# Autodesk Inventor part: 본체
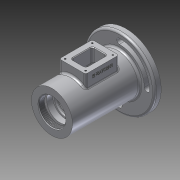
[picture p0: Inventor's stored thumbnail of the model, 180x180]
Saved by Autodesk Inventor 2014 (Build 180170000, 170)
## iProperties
Created: 2017-05
Part Number: 본체
Material: 알루미늄 6061
Document SubType Name: Modeling
Designer: oa51
Density: 2.71 g/cm^3
Appearance: 알루미늄 - 평지
Author: oa51
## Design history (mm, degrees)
sketch "스케치1"
  geometry: L1 (0, 57.5)-(0, -57.5); L2 (0, 57.5)-(31, 57.5); L3 (31, 57.5)-(31, -57.5); L4 (31, -57.5)-(22, -57.5); L5 (22, -57.5)-(16, -43.5); L6 (16, -43.5)-(12.904, -43.5); L7 (12.5, -36.2)-(10, -36.2); L8 (10, -36.2)-(10, -33.5); L9 (16.5, -33.5)-(16.5, -28.5); L10 (16.5, -28.5)-(17.5, -28.5); L11 (17.5, -28.5)-(17.5, -17.5); L12 (17.5, -17.5)-(26, -17.5); L13 (26, -17.5)-(26, 20.5); L14 (26, 20.5)-(17.5, 20.5); L15 (17.5, 20.5)-(17.5, 31.5); L16 (17.5, 31.5)-(18.5, 31.5); L17 (18.5, 31.5)-(18.5, 33.25); L18 (18.5, 33.25)-(17.5, 33.25); L19 (24, 48.5)-(0, 48.5); L20 (10, -33.5)-(16.5, -33.5); L21 (17.5, 33.25)-(17.5, 36.5); L22 (17.5, 36.5)-(20, 36.5); L23 (20, 36.5)-(20, 45.5); L24 (20, 45.5)-(24, 45.5); L25 (24, 45.5)-(24, 48.5); L26 (12.5, -36.2)-(12.5, -42.8); L27 (12.5, -42.8)-(12.904, -43.5); 2 further points
  constraints: 54 end point, 19 parallel, 5 perpendicular, 1 coincident, 1 horizontal alignment, 1 midpoint, 1 point on line, 1 vertical
  dimensions: "d0" = 115 distance of L1.start L1.end; "d1" = 62 diameter of L3 L1; "d2" = 32 diameter of L5.end L1; "d4" = 20 diameter of L8 L1; "d5" = 33 diameter of L9 L1; "d6" = 35 diameter of L11 L1; "d7" = 52 diameter of L13 L1; "d9" = 37 diameter of L17 L1; "d12" = 14 vertical distance of L1.end L5.end; "d14" = 7.3 vertical distance of L6.end L7.end; "d15" = 2.7 distance of L7.end L8.end; "d16" = 5 distance of L9.start L9.end; "d17" = 11 distance of L10.end L11.end; "d18" = 38 distance of L12.end L13.end; "d19" = 11 distance of L14.end L15.end; "d20" = 1.75 distance of L16.end L17.end; "d21" = 35 diameter of L15 L1; "d22" = 12 vertical distance of L23.end L1.start; "d23" = 3 distance of L24.end L19.start; "d24" = 48 diameter of L25 L1; "d25" = 40 diameter of L23 L1; "d26" = 35 diameter of L21 L1; "d27" = 21 vertical distance of L1.start L21.end; "d28" = 44 diameter of L4.end L1; "d62" = 30 deg angle of L26 L27; "d63" = 25 diameter of L26 L1; "d64" = 0.7 vertical distance of L6.end L26.end
revolve "회전1" sketch "스케치1" stored, may be unused: angle "d29" = 90 deg
hole "구멍1" diameter "d32" = 40.376; stored, may be unused: countersink angle "d36" = 90 deg, drill point angle "d38" = 0 deg; dims "d30" = 10, "d31" = 10, "d33" = 11, "d34" = 4, "d35" = 2, "d37" = 11
node "작업 평면1"
sketch "스케치2"
  geometry: L1 (20, 26.5)-(-20, 26.5); L2 (-20, 26.5)-(-20, -23.5); L3 (-20, -23.5)-(20, -23.5); L4 (20, -23.5)-(20, 26.5); L5 (-31, 57.5)-(31, 57.5) reference; 2 further points
  constraints: 8 end point, 2 parallel, 1 horizontal, 1 midpoint, 1 perpendicular, 1 vertical alignment
  dimensions: "d40" = 40 distance of L3.end L2.end; "d41" = 50 distance of L2.end L1.end; "d42" = 31 distance between parallel lines of L5 L1
extrude "돌출1" join sketch "스케치2" stored distance "d43" = 10; taper "d44" = 0 deg
sketch "스케치3"
  geometry: L1 (-20, -26.5)-(20, -26.5) reference; L2 (-20, 23.5)-(-20, -26.5) reference; L3 (-11, -17.5)-(11, -17.5); L4 (11, -17.5)-(11, 14.5); L5 (11, 14.5)-(-11, 14.5); L6 (-11, 14.5)-(-11, -17.5); 5 further points
  constraints: 8 end point, 4 midpoint, 2 parallel, 1 horizontal, 1 horizontal alignment, 1 perpendicular, 1 vertical alignment
  dimensions: "d45" = 22 distance of L5.end L4.end; "d46" = 32 distance of L4.end L3.end
extrude "돌출2" cut sketch "스케치3" distance "d47" = 50; taper "d48" = 0 deg
node "작업 평면2"
sketch "스케치4"
  geometry: C1 r 31 at (0, 0) reference; C2 r 53 at (0, 0); 1 further point
  constraints: 1 centre point, 1 coincident
  dimensions: "d50" = 106 diameter of C2
extrude "돌출3" join sketch "스케치4" distance "d51" = 10; taper "d52" = 0 deg
sketch "스케치5"
  geometry: C1 r 31 at (0, 0) reference; C2 r 53 at (0, 0) reference; A1 r 4 centre (0, 41.5) between (0, 37.5) and (0, 45.5); A2 r 4 centre (-41.5, 0) between (-45.5, 0) and (-37.5, 0); A3 r 4 centre (0, -41.5) between (0, -37.5) and (0, -45.5); A4 r 4 centre (41.5, 0) between (45.5, 0) and (37.5, 0); A5 r 45.5 centre (0, 0) between (0, -45.5) and (45.5, 0); A6 r 45.5 centre (0, 0) between (0, 45.5) and (-45.5, 0); A7 r 37.5 centre (0, 0) between (0, -37.5) and (37.5, 0); A8 r 37.5 centre (0, 0) between (0, 37.5) and (-37.5, 0)
  constraints: 16 point on circle, 8 centre point, 2 coincident, 2 horizontal alignment
  dimensions: "d56" = 8 diameter of A1; "d57" = 8 diameter of A2; "d59" = 8 diameter of A4
extrude "돌출4" cut sketch "스케치5" distance "d60" = 10; taper "d61" = 0 deg
fillet "모깎기1" dims "d68" = 3
chamfer "모따기2" distance "d69" = 1; stored, may be unused: second distance "d70" = 2, angle "d71" = 45 deg
fillet "모깎기2" dims "d72" = 3
chamfer "모따기3" distance "d73" = 1; stored, may be unused: second distance "d74" = 2, angle "d75" = 45 deg
fillet "모깎기3" dims "d76" = 3
fillet "모깎기4" dims "d77" = 3
fillet "모깎기5" dims "d78" = 3
fillet "모깎기6" dims "d79" = 0.3
fillet "모깎기7" dims "d80" = 3
sketch "스케치6"
  geometry: L1 (-12, 11.5)-(-12, -14.5) reference; L2 (-12, -1.5)-(-8, -1.5); 2 further points
  constraints: 2 end point, 1 midpoint, 1 perpendicular
  dimensions: "d81" = 15.5 horizontal distance of point (0, 0) point (-15.5, -22); "d82" = 20.5 distance from line of point (-15.5, -22) L2
hole "구멍2" sketch "스케치6" at (-15.5, -22) diameter "d83" = 2.459; stored, may be unused: countersink angle "d87" = 90 deg, drill point angle "d89" = 118 deg; dims "d84" = 6, "d85" = 4, "d86" = 2, "d88" = 8
sketch "스케치7"
  geometry: L1 (0, 0)-(44, 0) reference; L2 (-34, -75)-(-34, -13) reference; 2 further points
  constraints: 1 other
  dimensions: "d96" = 56 distance from line of L2 point (22, -8); "d97" = 8 distance from line of L1 point (22, -8)
feature "엠보싱1" sketch "스케치7" dims "d0" = 115, "d1" = 62, "d2" = 32, "d4" = 20, "d5" = 33, "d6" = 35, "d7" = 52, "d9" = 37, "d12" = 14, "d14" = 7.3, "d15" = 2.7, "d16" = 5, "d17" = 11, "d18" = 38, "d19" = 11, "d20" = 1.75, "d21" = 35, "d22" = 12, "d23" = 3, "d24" = 48, "d25" = 40, "d26" = 35, "d27" = 21, "d28" = 44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
node "솔리드1"
pattern_linear "직사각형 패턴1" dims "d92" = 41, "d95" = 31
other parameters: "d39" = 44, "d49" = -3, "d53" = 91, "d54" = 75
